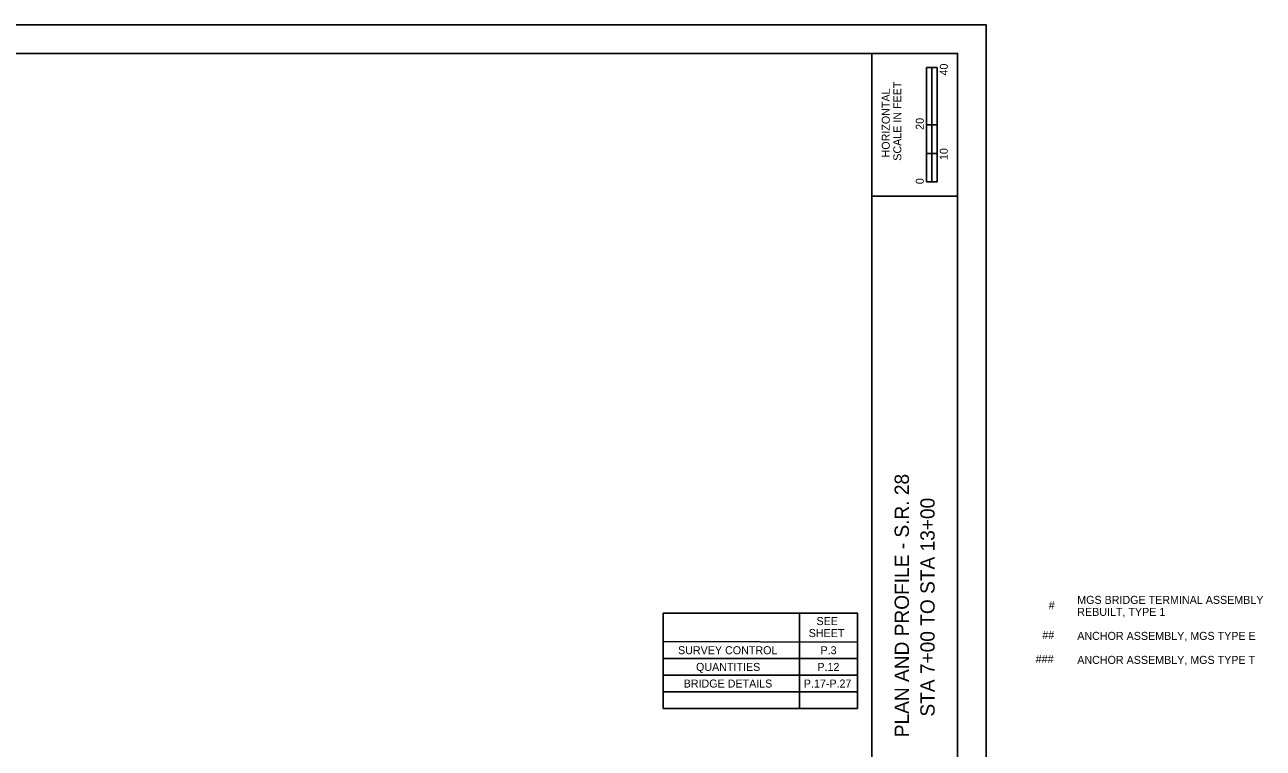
# Model space of a CAD drawing. Extents: x -4.5 to 38.8, y 0 to 22.
# Drawn here: x 17.19 to 38.85, y 9.34 to 22 of the extents above; entities that cross this region are included whole.
import ezdxf

# ---------------------------------------------------------------- set-up
doc = ezdxf.new("R2010")
doc.units = 0
for name, color, linetype in [('SH_Border', 7, 'Continuous'), ('SH_Cut_Line', 7, 'Continuous'), ('SH_Data', 7, 'Continuous'), ('SH_Text', 7, 'Continuous'), ('TX_P_20', 7, 'Continuous')]:
    doc.layers.add(name, color=color, linetype=linetype)

msp = doc.modelspace()

# ---------------------------------------------------------------- linework, layer by layer
at = {"layer": 'SH_Border'}
for p, q in [((32, 0.5), (32, 21.5)), ((32, 19), (33.5, 19))]:
    msp.add_line(p, q, dxfattribs=at)
msp.add_lwpolyline([(1.5, 21.5), (33.5, 21.5), (33.5, 0.5), (1.5, 0.5)], close=True, dxfattribs=at)
at = {"layer": 'SH_Cut_Line'}
msp.add_lwpolyline([(0, 0), (34, 0), (34, 22), (0, 22)], close=True, dxfattribs=at)
at = {"layer": 'SH_Data'}
for p, q in [((32.957, 19.25), (32.957, 21.25)), ((33.144, 21.25), (32.957, 21.25)), ((32.957, 20.25), (32.957, 21.25)), ((32.957, 21.25), (33.05, 21.25)), ((33.05, 21.25), (33.051, 21.25)), ((33.051, 21.25), (33.051, 20.25)), ((33.144, 21.25), (33.144, 19.25)), ((33.051, 20.25), (32.957, 20.25)), ((33.143, 20.25), (33.05, 20.25)), ((33.05, 20.25), (33.05, 19.75)), ((33.143, 19.75), (33.143, 20.25)), ((33.05, 19.75), (32.957, 19.75)), ((32.957, 19.75), (32.957, 19.25)), ((33.05, 19.25), (33.05, 19.75)), ((33.05, 19.75), (33.143, 19.75)), ((33.144, 19.25), (32.957, 19.25)), ((32.957, 19.25), (33.05, 19.25))]:
    msp.add_line(p, q, dxfattribs=at)
at = {"layer": 'TX_P_20'}
for p, q in [((30.736, 11.705), (30.736, 10.04)), ((28.352, 11.207), (31.753, 11.2)), ((28.352, 10.915), (31.753, 10.915)), ((28.352, 10.623), (31.753, 10.623)), ((28.352, 10.332), (31.753, 10.332)), ((28.352, 10.04), (31.753, 10.04))]:
    msp.add_line(p, q, dxfattribs=at)
msp.add_lwpolyline([(28.352, 11.705), (31.753, 11.705), (31.753, 10.04), (28.352, 10.04)], close=True, dxfattribs=at)

# ---------------------------------------------------------------- texts
at = {"layer": 'SH_Data'}
for s, height, p in [('40', 0.14, (33.33, 21.112)), ('HORIZONTAL', 0.14, (32.315, 19.679)), ('SCALE IN FEET', 0.14, (32.517, 19.621)), ('20', 0.14, (32.91, 20.162)), ('10', 0.14, (33.33, 19.633)), ('0', 0.14, (32.91, 19.211)), ('PLAN AND PROFILE - S.R. 28', 0.25, (32.65, 9.535)), ('STA 7+00 TO STA 13+00', 0.25, (33.1, 9.896))]:
    msp.add_text(s, height=height, rotation=90, dxfattribs=at).set_placement(p)
at = {"layer": 'SH_Text'}
for s, p in [('MGS BRIDGE TERMINAL ASSEMBLY', (35.594, 11.868)), ('#', (35.094, 11.772)), ('REBUILT, TYPE 1', (35.594, 11.658)), ('##', (34.982, 11.255)), ('ANCHOR ASSEMBLY, MGS TYPE E', (35.594, 11.238)), ('###', (34.868, 10.835)), ('ANCHOR ASSEMBLY, MGS TYPE T', (35.594, 10.818))]:
    msp.add_text(s, height=0.14, rotation=360, dxfattribs=at).set_placement(p)
at = {"layer": 'TX_P_20'}
for s, p in [('SEE ', (31.034, 11.497)), ('SHEET', (30.898, 11.287)), ('SURVEY CONTROL', (28.613, 10.987)), ('P.3', (31.104, 10.987)), ('QUANTITIES', (28.927, 10.695)), ('P.12', (31.049, 10.695)), ('BRIDGE DETAILS', (28.711, 10.404)), ('P.17-P.27', (30.812, 10.404))]:
    msp.add_text(s, height=0.14, dxfattribs=at).set_placement(p)

doc.saveas('drawing.dxf')
